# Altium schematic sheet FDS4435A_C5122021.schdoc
size 127 x 101 mm
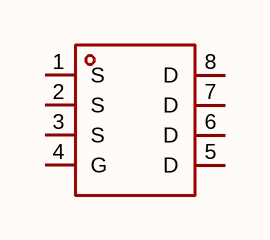
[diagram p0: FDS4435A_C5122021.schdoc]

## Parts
Q?  fds4435a_c5122021  [SOP-8_L4.9-W3.9-P1.27-LS6.0-BL]  (value not drawn)

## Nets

Not connected (* = marked no-connect by the designer): Q? 1(S) 2(S) 3(S) 4(G) 5(D) 6(D) 7(D) 8(D)

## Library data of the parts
Q? = fds4435a_c5122021: 漏源电压(Vdss):30V;连续漏极电流(Id):12A;导通电阻(RDS(on)):9.5mΩ@10V;耗散功率(Pd):3W;阈值电压(Vgs(th)):1.5V;; Manufacturer: TECH PUBLIC(台舟); AddInBom: yes; ModelId: 75c24a7891ee4dd6bdac16a7163ff87e; ModelName: SOP-8_L4.9-W3.9-P1.27-LS6.0-BL-1; ModelTransform: 192.913,236.22,0,0,0,0,-0.393,2.749,0; Drain to Source Voltage: 30V; Current - Continuous Drain(Id): 12A; Pd - Power Dissipation: 3W; Gate Threshold Voltage (Vgs(th)): 1.5V; Gate Charge(Qg): 25nC; Input Capacitance(Ciss): 1.2nF@15V; Reverse Transfer Capacitance (Crss@Vds): 150pF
